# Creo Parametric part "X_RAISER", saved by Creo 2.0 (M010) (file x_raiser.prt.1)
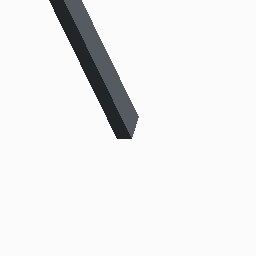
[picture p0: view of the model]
Units: Inch lbm Second (Pro/E Default); INCH, POUND, SECS

Created from: INLBS_PART_SOLID.PRT

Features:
  1. datum plane "RIGHT"
  2. datum plane "TOP"
  3. datum plane "FRONT"
  4. coordinate system
  5. sketch "Sketch 1"
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
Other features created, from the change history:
  extrusion "Extrude 1"

Surfaces: 9 plane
